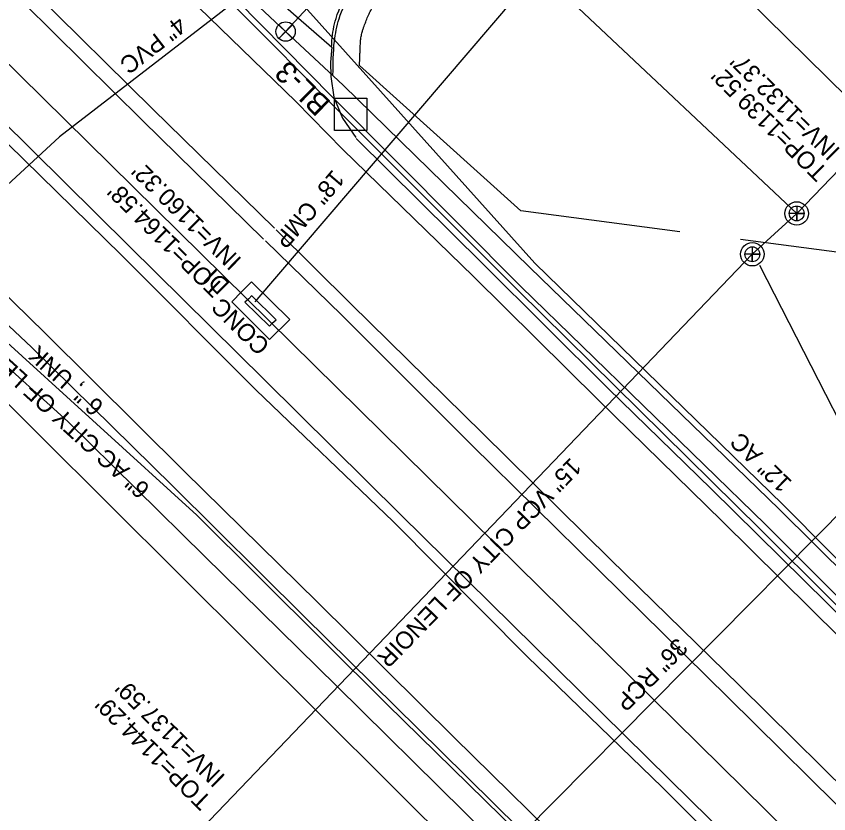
# Model space of a CAD drawing. Extents: x 1263837 to 1268319, y 770628 to 773628.
# Drawn here: x 1267398.4 to 1267585.3, y 771382.1 to 771565.6 of the extents above; entities that cross this region are included whole.
import ezdxf

# ---------------------------------------------------------------- set-up
doc = ezdxf.new("R2010")
doc.units = 0
for name, color, linetype in [('CTL Secondary Horizontal and Vertical Text', 7, 'Continuous'), ('Exist Guardrail', 7, 'Continuous'), ('Exist Other Culture Area Outline', 7, 'Continuous'), ('Exist Other Culture Area Outline Text', 7, 'Continuous'), ('Exist Structure Minor Drop Inlet', 7, 'Continuous'), ('Exist Structure Minor Drop Inlet Text', 7, 'Continuous'), ('Exist Structure Minor Drop Inlet Top Elevation', 7, 'Continuous'), ('Exist Structure Minor Pipes RCP 36 Inch', 7, 'Continuous'), ('Exist Structure Minor Pipes RCP 36 Inch Text', 7, 'Continuous'), ('Exist Utilities Gas UG Line SUE LOS B', 7, 'Continuous'), ('Exist Utilities Gas UG Line SUE LOS B Text', 7, 'Continuous'), ('Exist Utilities Telephone UG Cable SUE LOS B', 7, 'Continuous'), ('Exist Utilities Telephone UG FO SUE LOS B', 7, 'Continuous'), ('Exist Utilities Water UG Line SUE LOS B', 7, 'Continuous'), ('Exist Utilities Water UG Line SUE LOS B Text', 7, 'Continuous'), ('Exist Utilities Water Valve CELL', 7, 'Continuous'), ('Exist Vegetation Woods Line', 7, 'Continuous'), ('Pattern 2', 7, 'Continuous'), ('Prop CMT Slope Fill', 7, 'Continuous'), ('Prop Drainage Structure Pipe RCP 30in Class III Label', 7, 'Continuous'), ('Prop Drainage Structure Pipe RCP 42in Class III', 7, 'Continuous'), ('Prop Drainage Structure Plot Symbol 20 Scale CELL', 7, 'Continuous'), ('Prop Horizontal Alignment', 7, 'Continuous'), ('Prop Retaining Wall', 7, 'Continuous'), ('Prop SS Fill Line', 7, 'Continuous'), ('Prop SS Fill Text', 7, 'Continuous'), ('Prop SS Transition Line', 7, 'Continuous'), ('Prop WCR CELL', 7, 'Continuous'), ('Scratch_Level_0', 7, 'Continuous'), ('Scratch_Level_2', 7, 'Continuous'), ('Scratch_Level_5', 7, 'Continuous')]:
    doc.layers.add(name, color=color, linetype=linetype)

# ---------------------------------------------------------------- blocks, each defined once
blk = doc.blocks.new('EXIST UTILITIES SANITARY SEWER MANHOLE')
at = {"layer": 'Prop WCR CELL'}
blk.add_lwpolyline([(0, 0.03425), (0, -0.03425), (0, 0), (0.03425, 0), (-0.03425, 0)], dxfattribs=at)
for radius in [0.05389, 0.03425]:
    blk.add_circle((0, 0), radius, dxfattribs=at)
blk = doc.blocks.new('CTL SECONDARY HORIZONTAL AND VERTICAL')
at = {"layer": 'Prop CMT Slope Fill'}
blk.add_line((0, 0), (0, 0), dxfattribs=at)
blk.add_lwpolyline([(-0.1043, 0.0004), (0.0005, 0.1052), (0.1055, 0.0002), (0.0007, -0.1047)], close=True, dxfattribs=at)
blk = doc.blocks.new('EXIST UTILITIES WATER VALVE')
at = {"layer": 'Exist Utilities Water Valve CELL'}
blk.add_lwpolyline([(0.0315, 0.0315), (-0.0315, -0.0315), (0, 0), (0.0315, -0.0315), (-0.0315, 0.0315)], dxfattribs=at)
blk.add_circle((0, 0), 0.0445, dxfattribs=at)

msp = doc.modelspace()

# ---------------------------------------------------------------- linework, layer by layer
at = {"layer": 'Exist Guardrail'}
msp.add_lwpolyline([(1267619.49, 771265.06), (1267589.62, 771295.18), (1267559.02, 771325.48), (1267531.24, 771353.13), (1267501.45, 771382.53), (1267472.07, 771411.47), (1267441.71, 771441.32), (1267410.26, 771472.3), (1267391.71, 771489.04)], dxfattribs=at)
msp.add_lwpolyline([(1267619.49, 771265.06), (1267589.62, 771295.18), (1267559.02, 771325.48), (1267531.24, 771353.13), (1267501.45, 771382.53), (1267472.07, 771411.47), (1267441.71, 771441.32), (1267410.26, 771472.3), (1267391.71, 771489.04)], dxfattribs=at)
msp.add_lwpolyline([(1267619.49, 771265.06), (1267589.62, 771295.18), (1267559.02, 771325.48), (1267531.24, 771353.13), (1267501.45, 771382.53), (1267472.07, 771411.47), (1267441.71, 771441.32), (1267410.26, 771472.3), (1267391.71, 771489.04)], dxfattribs=at)
msp.add_lwpolyline([(1267619.49, 771265.06), (1267589.62, 771295.18), (1267559.02, 771325.48), (1267531.24, 771353.13), (1267501.45, 771382.53), (1267472.07, 771411.47), (1267441.71, 771441.32), (1267410.26, 771472.3), (1267391.71, 771489.04)], dxfattribs=at)
at = {"layer": 'Exist Other Culture Area Outline'}
msp.add_lwpolyline([(1267452.51, 771504.43), (1267450.29, 771502.22), (1267447.95, 771499.83), (1267456.65, 771491.22), (1267461.33, 771495.8), (1267452.52, 771504.47)], dxfattribs=at)
at = {"layer": 'Exist Structure Minor Drop Inlet'}
msp.add_lwpolyline([(1267452.58, 771501.27), (1267452.57, 771501.32), (1267451.85, 771500.54), (1267450.94, 771499.77), (1267456.67, 771494.24), (1267457.27, 771494.92), (1267458.18, 771495.73), (1267452.58, 771501.27)], dxfattribs=at)
at = {"layer": 'Exist Structure Minor Pipes RCP 36 Inch'}
msp.add_line((1267484.85, 771347.21), (1267609.74, 771473.42), dxfattribs=at)
at = {"layer": 'Exist Utilities Gas UG Line SUE LOS B'}
for points in [[(1268032.93, 770994.26), (1267939.14, 771106.42), (1267894.31, 771153.65), (1267866.26, 771181.88), (1267808.35, 771229.56), (1267766.55, 771267.35), (1267713.16, 771307.91), (1267667.2, 771353.59), (1267619.33, 771400.39), (1267603.56, 771415.83), (1267570.68, 771448.69), (1267514.57, 771503.28), (1267471.16, 771546.94), (1267449.13, 771569.31), (1267442.48, 771576.9), (1267413.75, 771608.31), (1267408.43, 771614.09), (1267384.91, 771637.16), (1267351.56, 771671.29), (1267306.37, 771718.78), (1267260.52, 771767.18), (1267251.66, 771778.25)], [(1267449.13, 771569.31), (1267408.34, 771537.8), (1267373.27, 771505.54), (1267306.4, 771448.69)]]:
    msp.add_lwpolyline(points, dxfattribs=at)
at = {"layer": 'Exist Utilities Telephone UG Cable SUE LOS B'}
msp.add_lwpolyline([(1267956.46, 771082.6), (1267948.96, 771075.88), (1267931.05, 771095.71), (1267882.26, 771146.49), (1267859.68, 771168.91), (1267802.94, 771223.87), (1267764.94, 771261.15), (1267712.13, 771307.04), (1267666.26, 771352.44), (1267617.91, 771399.06), (1267602.49, 771414.74), (1267569.55, 771447.53), (1267513.89, 771502.51), (1267469.9, 771546.45), (1267457.47, 771559.02), (1267421.92, 771594.61), (1267382.05, 771633.09), (1267347.13, 771666.37), (1267296.56, 771716.62), (1267252.57, 771760), (1267248.32, 771784.89), (1267236.47, 771776.22), (1267198.93, 771813.02), (1267164.82, 771845.39)], dxfattribs=at)
at = {"layer": 'Exist Utilities Telephone UG FO SUE LOS B'}
msp.add_lwpolyline([(1268035.78, 770997.15), (1267940.84, 771107.94), (1267897.35, 771156.24), (1267867.85, 771183.87), (1267810.07, 771229.4), (1267770.21, 771268.8), (1267721.65, 771316.15), (1267671.88, 771358.99), (1267623.8, 771405.23), (1267607.14, 771420.63), (1267574.79, 771453.25), (1267517.7, 771508.8), (1267479.52, 771551.33), (1267465.41, 771567.06), (1267416.72, 771620.51), (1267391.64, 771647.4), (1267311.09, 771724.38), (1267266.64, 771768.8), (1267249.06, 771785.93), (1267211.37, 771825.47), (1267176.84, 771861.92), (1267114.4, 771928.7), (1267064.3, 771976.43)], dxfattribs=at)
at = {"layer": 'Exist Utilities Water UG Line SUE LOS B'}
for points in [[(1267460.35, 771562.06), (1267407.65, 771611.49), (1267384.09, 771634.71), (1267349.53, 771669.13), (1267303.81, 771713.68), (1267255.61, 771762.88), (1267237.59, 771778.93), (1267200.46, 771814.35), (1267167.14, 771847.51), (1267158.06, 771856.95), (1267162.99, 771862.03)], [(1267460.35, 771562.06), (1267482.94, 771586.46), (1267507.08, 771615.3), (1267550.56, 771666.39), (1267559.06, 771677.39)], [(1268030.4, 770991.7), (1267933.04, 771099.64), (1267886.11, 771148), (1267862.1, 771174.24), (1267808.15, 771226.67), (1267768.43, 771263.33), (1267718.14, 771311.73), (1267669.59, 771357.26), (1267623.09, 771404.13), (1267606.61, 771419.77), (1267573.94, 771452.13), (1267516.52, 771507.78), (1267473.59, 771549.74), (1267460.35, 771562.06)], [(1267653, 771234.75), (1267626.18, 771266.46), (1267577.79, 771315), (1267536.41, 771355.55), (1267483.66, 771407.27), (1267439.95, 771450.78), (1267393.7, 771492.8), (1267375.26, 771507.98)]]:
    msp.add_lwpolyline(points, dxfattribs=at)
at = {"layer": 'Exist Vegetation Woods Line'}
for points in [[(1267551.06, 771516.01), (1267514.5, 771520.8), (1267477.35, 771554.28)], [(1267850.76, 771404.04), (1267787.96, 771399.05), (1267680.49, 771459.91), (1267633.2, 771505.25), (1267565.02, 771514.19)], [(1267351.54, 771481.9), (1267362.16, 771490.76), (1267387.33, 771485.46), (1267613.96, 771259.89), (1267583.99, 771226.31)]]:
    msp.add_lwpolyline(points, dxfattribs=at)
msp.add_open_spline([(1267477.35, 771554.28), (1267477.42, 771555.97), (1267477.49, 771557.7), (1267477.56, 771559.45), (1267477.57, 771559.51), (1267477.57, 771559.54), (1267477.57, 771559.56), (1267477.57, 771559.57), (1267477.57, 771559.62), (1267477.58, 771559.75), (1267477.59, 771559.89), (1267477.61, 771560.16), (1267477.64, 771560.35), (1267477.73, 771560.93), (1267477.82, 771561.35), (1267477.99, 771562.01), (1267478.05, 771562.23), (1267478.2, 771562.7), (1267478.27, 771562.93), (1267478.53, 771563.67), (1267478.71, 771564.16), (1267479.31, 771565.63), (1267479.76, 771566.6), (1267480.4, 771567.87), (1267480.53, 771568.12), (1267480.68, 771568.41), (1267480.7, 771568.46), (1267480.73, 771568.51), (1267480.75, 771568.54), (1267480.76, 771568.56), (1267480.8, 771568.65), (1267480.92, 771568.87), (1267481.03, 771569.08), (1267481.4, 771569.8), (1267481.7, 771570.37), (1267482.56, 771572.03), (1267483.11, 771573.1), (1267484.23, 771575.13), (1267484.79, 771576.09), (1267485.66, 771577.42), (1267485.95, 771577.85), (1267486.4, 771578.47), (1267486.55, 771578.67), (1267486.71, 771578.88), (1267486.71, 771578.88), (1267486.72, 771578.9), (1267486.73, 771578.9), (1267486.75, 771578.93), (1267486.78, 771578.97), (1267486.87, 771579.08), (1267487.04, 771579.3), (1267487.95, 771580.47), (1267490.35, 771583.57), (1267495.74, 771590.51), (1267500.35, 771596.45), (1267503.43, 771600.41)], degree=3, dxfattribs=at)
at = {"layer": 'Pattern 2'}
msp.add_lwpolyline([(1267569.4, 771508.28), (1267603.03, 771442.51), (1267607.3, 771438.3)], dxfattribs=at)
at = {"layer": 'Prop Drainage Structure Pipe RCP 42in Class III'}
msp.add_line((1267453.34, 771499.89), (1267535.14, 771595.51), dxfattribs=at)
at = {"layer": 'Prop Horizontal Alignment'}
msp.add_line((1268113.05, 771031.32), (1267144.12, 771985.71), dxfattribs=at)
at = {"layer": 'Prop SS Fill Line'}
msp.add_spline([(1267471.25, 771552.08), (1267471.58, 771559.83), (1267472.65, 771565.01), (1267475.43, 771571.32), (1267481.99, 771582.57), (1267498.71, 771604.12)], degree=3, dxfattribs=at)
at = {"layer": 'Prop SS Fill Text'}
for points in [[(1267455.25, 771514.29), (1267427.43, 771541.62), (1267400.12, 771568.57), (1267372.32, 771596.01), (1267340.08, 771628.19), (1267310.1, 771656.99), (1267279.21, 771685.4), (1267248.96, 771712.93), (1267216.15, 771742.98), (1267185.9, 771770.94), (1267154.16, 771800.26), (1267123.77, 771828.98), (1267094.53, 771856.25), (1267062.43, 771886.08), (1267032.71, 771915.32), (1267003.31, 771945.43), (1266973.26, 771975.14), (1266941.46, 772007.96), (1266911.94, 772038.5), (1266853.53, 772099.1), (1266834.47, 772118.84), (1266823.63, 772130.08)], [(1267732.6, 771208.48), (1267701.1, 771239.46), (1267667.38, 771272.86), (1267646.27, 771293.49), (1267612.95, 771326.44), (1267581.07, 771358.13), (1267548.68, 771389.96), (1267517.68, 771420.47), (1267486.79, 771450.93), (1267455.58, 771481.86), (1267424.27, 771512.72), (1267394.61, 771542.04), (1267362.32, 771573.4), (1267330.89, 771604.89), (1267298.03, 771636.67), (1267266.54, 771667.78), (1267235.26, 771698.57), (1267202.31, 771731.05), (1267169.97, 771763.25), (1267139.21, 771793.38), (1267107.62, 771824.41), (1267076.99, 771855.19)], [(1267441.78, 771587.23), (1267456.22, 771571.37), (1267470.96, 771558.46), (1267470.66, 771555.01), (1267470.72, 771551.73), (1267471.42, 771546.95), (1267473.4, 771542.12), (1267476.49, 771537.65)], [(1267743.41, 771152.17), (1267710.08, 771185.53), (1267678.48, 771216.03), (1267661.63, 771232.59), (1267656.65, 771234.45), (1267642.2, 771249.43), (1267625.55, 771267.15), (1267623.87, 771269.9), (1267591.48, 771302.51), (1267559.61, 771334.12), (1267526.22, 771366.71), (1267496.16, 771396.37), (1267464.58, 771427.45), (1267434.31, 771457.52), (1267401.98, 771489.39), (1267386.12, 771504.13), (1267383.93, 771505.24), (1267366.67, 771522.42), (1267349.45, 771538.82), (1267345.34, 771544.8), (1267340.1, 771550.27), (1267309.26, 771580.81)], [(1267476.58, 771537.48), (1267505.88, 771508.45), (1267534.53, 771479.9), (1267558.3, 771456.83), (1267590.24, 771425.33), (1267617.89, 771398.63), (1267646.26, 771370.63), (1267674.51, 771342.61), (1267702.24, 771314.76), (1267730.63, 771287.49), (1267757.08, 771260.99), (1267784.76, 771233.93), (1267811.59, 771207.46), (1267838.96, 771180.46), (1267866.14, 771153.49)], [(1268083.5, 770893.78), (1268054.88, 770922.29), (1268028.69, 770948.08), (1268000.36, 770976.02), (1267971.7, 771004.37), (1267943.06, 771032.84), (1267914.12, 771061.57), (1267885.82, 771089.69), (1267857.52, 771117.84), (1267828.26, 771146.71), (1267798.79, 771175.75), (1267769.54, 771204.51), (1267739.64, 771233.76), (1267709.41, 771263.56), (1267679.8, 771292.8), (1267652.41, 771319.73), (1267622.73, 771349.02), (1267593.06, 771378.31), (1267562.17, 771408.84), (1267532.49, 771438), (1267503.19, 771466.89), (1267473.31, 771496.78), (1267455.75, 771513.94)]]:
    msp.add_lwpolyline(points, dxfattribs=at)
msp.add_spline([(1267470.93, 771558.64), (1267471.01, 771559.99), (1267471.95, 771565.08), (1267474.95, 771571.86), (1267481.41, 771582.84), (1267498.37, 771604.73)], degree=3, dxfattribs=at)
at = {"layer": 'Prop SS Transition Line'}
for points in [[(1267147, 771855.87), (1267172.96, 771830.15), (1267204.32, 771799.37), (1267233.39, 771770.81), (1267261.9, 771743.08), (1267275.05, 771730.22), (1267294.7, 771711), (1267322.26, 771684.09), (1267338.25, 771668.39), (1267366.36, 771640.44), (1267393.59, 771613.84), (1267416.72, 771590.93), (1267435.37, 771572.48), (1267462.72, 771545.98), (1267473.52, 771534.95), (1267503.59, 771505.68)], [(1267730.96, 771207.25), (1267699.71, 771237.64), (1267665.94, 771271.22), (1267644.55, 771291.79), (1267611.28, 771324.49), (1267579.22, 771356.04), (1267547.1, 771388.09), (1267515.96, 771418.28), (1267485.06, 771449.32), (1267453.58, 771479.56), (1267422.47, 771510.71), (1267392.64, 771539.85), (1267360.64, 771571.54), (1267328.83, 771602.72), (1267296.54, 771634.69), (1267264.38, 771665.61), (1267233.37, 771696.71), (1267200.66, 771729.03), (1267168.07, 771761.48), (1267137.08, 771791.22), (1267105.97, 771822.92), (1267075.27, 771852.97)], [(1267457.81, 771516.79), (1267429.8, 771544.23), (1267402.28, 771571.41), (1267374.68, 771598.58), (1267342.2, 771630.72), (1267312.7, 771659.75)], [(1267746.48, 771155.58), (1267713.26, 771188.96), (1267681.78, 771219.9), (1267665.2, 771236.06), (1267647.66, 771253.76), (1267627.44, 771273.23), (1267594.51, 771306.06), (1267562.27, 771336.92), (1267529.11, 771370.17), (1267499.1, 771399.62), (1267467.63, 771430.8), (1267437.06, 771460.81), (1267405.04, 771492.63), (1267375.31, 771521.63), (1267343.02, 771553.29), (1267311.95, 771583.8)], [(1268086.22, 770896.97), (1268057.69, 770925.1), (1268031.56, 770950.8), (1268003.26, 770978.94), (1267974.3, 771007.28), (1267945.7, 771035.82), (1267916.96, 771064.3), (1267888.59, 771092.3), (1267860.01, 771120.5), (1267830.63, 771149.46), (1267801.46, 771178.39), (1267772.22, 771207.18), (1267742.54, 771236.63), (1267712.6, 771266.17), (1267682.67, 771295.53), (1267655.25, 771322.55), (1267625.53, 771351.77), (1267596.18, 771380.55), (1267564.78, 771411.57), (1267535.03, 771440.67), (1267505.64, 771469.65), (1267475.42, 771499.36), (1267458.2, 771516.4)], [(1267503.59, 771505.68), (1267532.35, 771477.23), (1267560.8, 771449.37), (1267587.89, 771422.62), (1267615.15, 771395.67), (1267643.54, 771367.65), (1267672.44, 771339.13), (1267700.05, 771312.37), (1267728.57, 771284.09), (1267754.73, 771258.49), (1267782.47, 771231.07), (1267809.16, 771204.83), (1267836.66, 771177.63), (1267863.8, 771150.77), (1267887.19, 771127.95), (1267909.67, 771105.32), (1267937.5, 771077.81), (1267964.96, 771050.54), (1267992.62, 771022.93), (1268020.94, 770995.26), (1268048.48, 770968), (1268076.9, 770940.07), (1268104, 770913.72)]]:
    msp.add_lwpolyline(points, dxfattribs=at)
at = {"layer": 'Scratch_Level_2'}
msp.add_line((1268021.82, 770938.71), (1267052.89, 771893.09), dxfattribs=at)
at = {"layer": 'Scratch_Level_5'}
for p, q in [((1267577.95, 771520.2), (1267283.38, 771797.71)), ((1267577.95, 771520.2), (1267691.37, 771637.92)), ((1267567.74, 771510.81), (1267577.95, 771520.2)), ((1267441.13, 771378.76), (1267567.74, 771510.81))]:
    msp.add_line(p, q, dxfattribs=at)

# ---------------------------------------------------------------- block references
at = {"layer": 'Exist Utilities Water Valve CELL', "xscale": 50, "yscale": 50}
msp.add_blockref('EXIST UTILITIES WATER VALVE', (1267460.35, 771562.06), dxfattribs=at)
at = {"layer": 'Prop CMT Slope Fill', "xscale": 50, "yscale": 49.99999999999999, "rotation": 44.99999999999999}
msp.add_blockref('CTL SECONDARY HORIZONTAL AND VERTICAL', (1267475.29, 771543), dxfattribs=at)
msp.add_blockref('CTL SECONDARY HORIZONTAL AND VERTICAL', (1267475.29, 771543), dxfattribs=at)
at = {"layer": 'Prop WCR CELL', "xscale": 50, "yscale": 50}
for p in [(1267577.95, 771520.2), (1267567.74, 771510.81)]:
    msp.add_blockref('EXIST UTILITIES SANITARY SEWER MANHOLE', p, dxfattribs=at)

# ---------------------------------------------------------------- texts
at = {"layer": 'CTL Secondary Horizontal and Vertical Text'}
msp.add_text('BL-3', height=5, rotation=135.4333, dxfattribs=at).set_placement((1267471, 771545.77))
at = {"layer": 'Exist Other Culture Area Outline Text'}
msp.add_text('CONC', height=4, rotation=135.4333, dxfattribs=at).set_placement((1267456.97, 771490.08))
at = {"layer": 'Exist Structure Minor Drop Inlet Text'}
msp.add_text('DI', height=4, rotation=135.4333, dxfattribs=at).set_placement((1267447.73, 771504.05))
at = {"layer": 'Exist Structure Minor Drop Inlet Top Elevation'}
msp.add_text("TOP=1164.58'", height=4, rotation=135.4333, dxfattribs=at).set_placement((1267446.38, 771503.47))
at = {"layer": 'Exist Structure Minor Pipes RCP 36 Inch Text'}
msp.add_text('36" RCP', height=4, rotation=225.3034, dxfattribs=at).set_placement((1267550.4, 771422.78))
at = {"layer": 'Exist Utilities Gas UG Line SUE LOS B Text'}
msp.add_text('4" PVC', height=4, rotation=217.6865, dxfattribs=at).set_placement((1267435.55, 771565.81))
at = {"layer": 'Exist Utilities Water UG Line SUE LOS B Text'}
for s, rotation, p in [('6" AC CITY OF LENOIR', 137.7395, (1267429.38, 771457.18)), ('6 ", UNK', 137.7395, (1267418.76, 771476.22)), ('12" AC', 135.8978, (1267577.08, 771458.47))]:
    msp.add_text(s, height=4, rotation=rotation, dxfattribs=at).set_placement(p)
at = {"layer": 'Prop Drainage Structure Pipe RCP 30in Class III Label'}
msp.add_text('18" CMP', height=4, rotation=229.4474, dxfattribs=at).set_placement((1267471.21, 771530.51))
at = {"layer": 'Prop Drainage Structure Plot Symbol 20 Scale CELL'}
msp.add_text("INV=1160.32'", height=4, rotation=135.4333, dxfattribs=at).set_placement((1267450.45, 771509.64))
at = {"layer": 'Prop Retaining Wall'}
for s, p in [("INV=1132.37'", (1267588.18, 771534.89)), ("TOP=1139.52'", (1267585.32, 771530.16)), ("INV=1137.59'", (1267446.68, 771390.64)), ("TOP=1144.29'", (1267443.56, 771385.43))]:
    msp.add_text(s, height=4, rotation=135.4333, dxfattribs=at).set_placement(p)
at = {"layer": 'Scratch_Level_0'}
msp.add_text('15" VCP CITY OF LENOIR', height=4, rotation=225.8162, dxfattribs=at).set_placement((1267525.94, 771464.24))

doc.saveas('drawing.dxf')
